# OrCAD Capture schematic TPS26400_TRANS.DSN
size C; title: TPS26400 40-V, 2-A Industrial eFuse With Integrated Reverse; rev: 1.2; note: Datasheet: SLVSDG2G     EVM: SLVUAV3; note: Input Polarity Protection
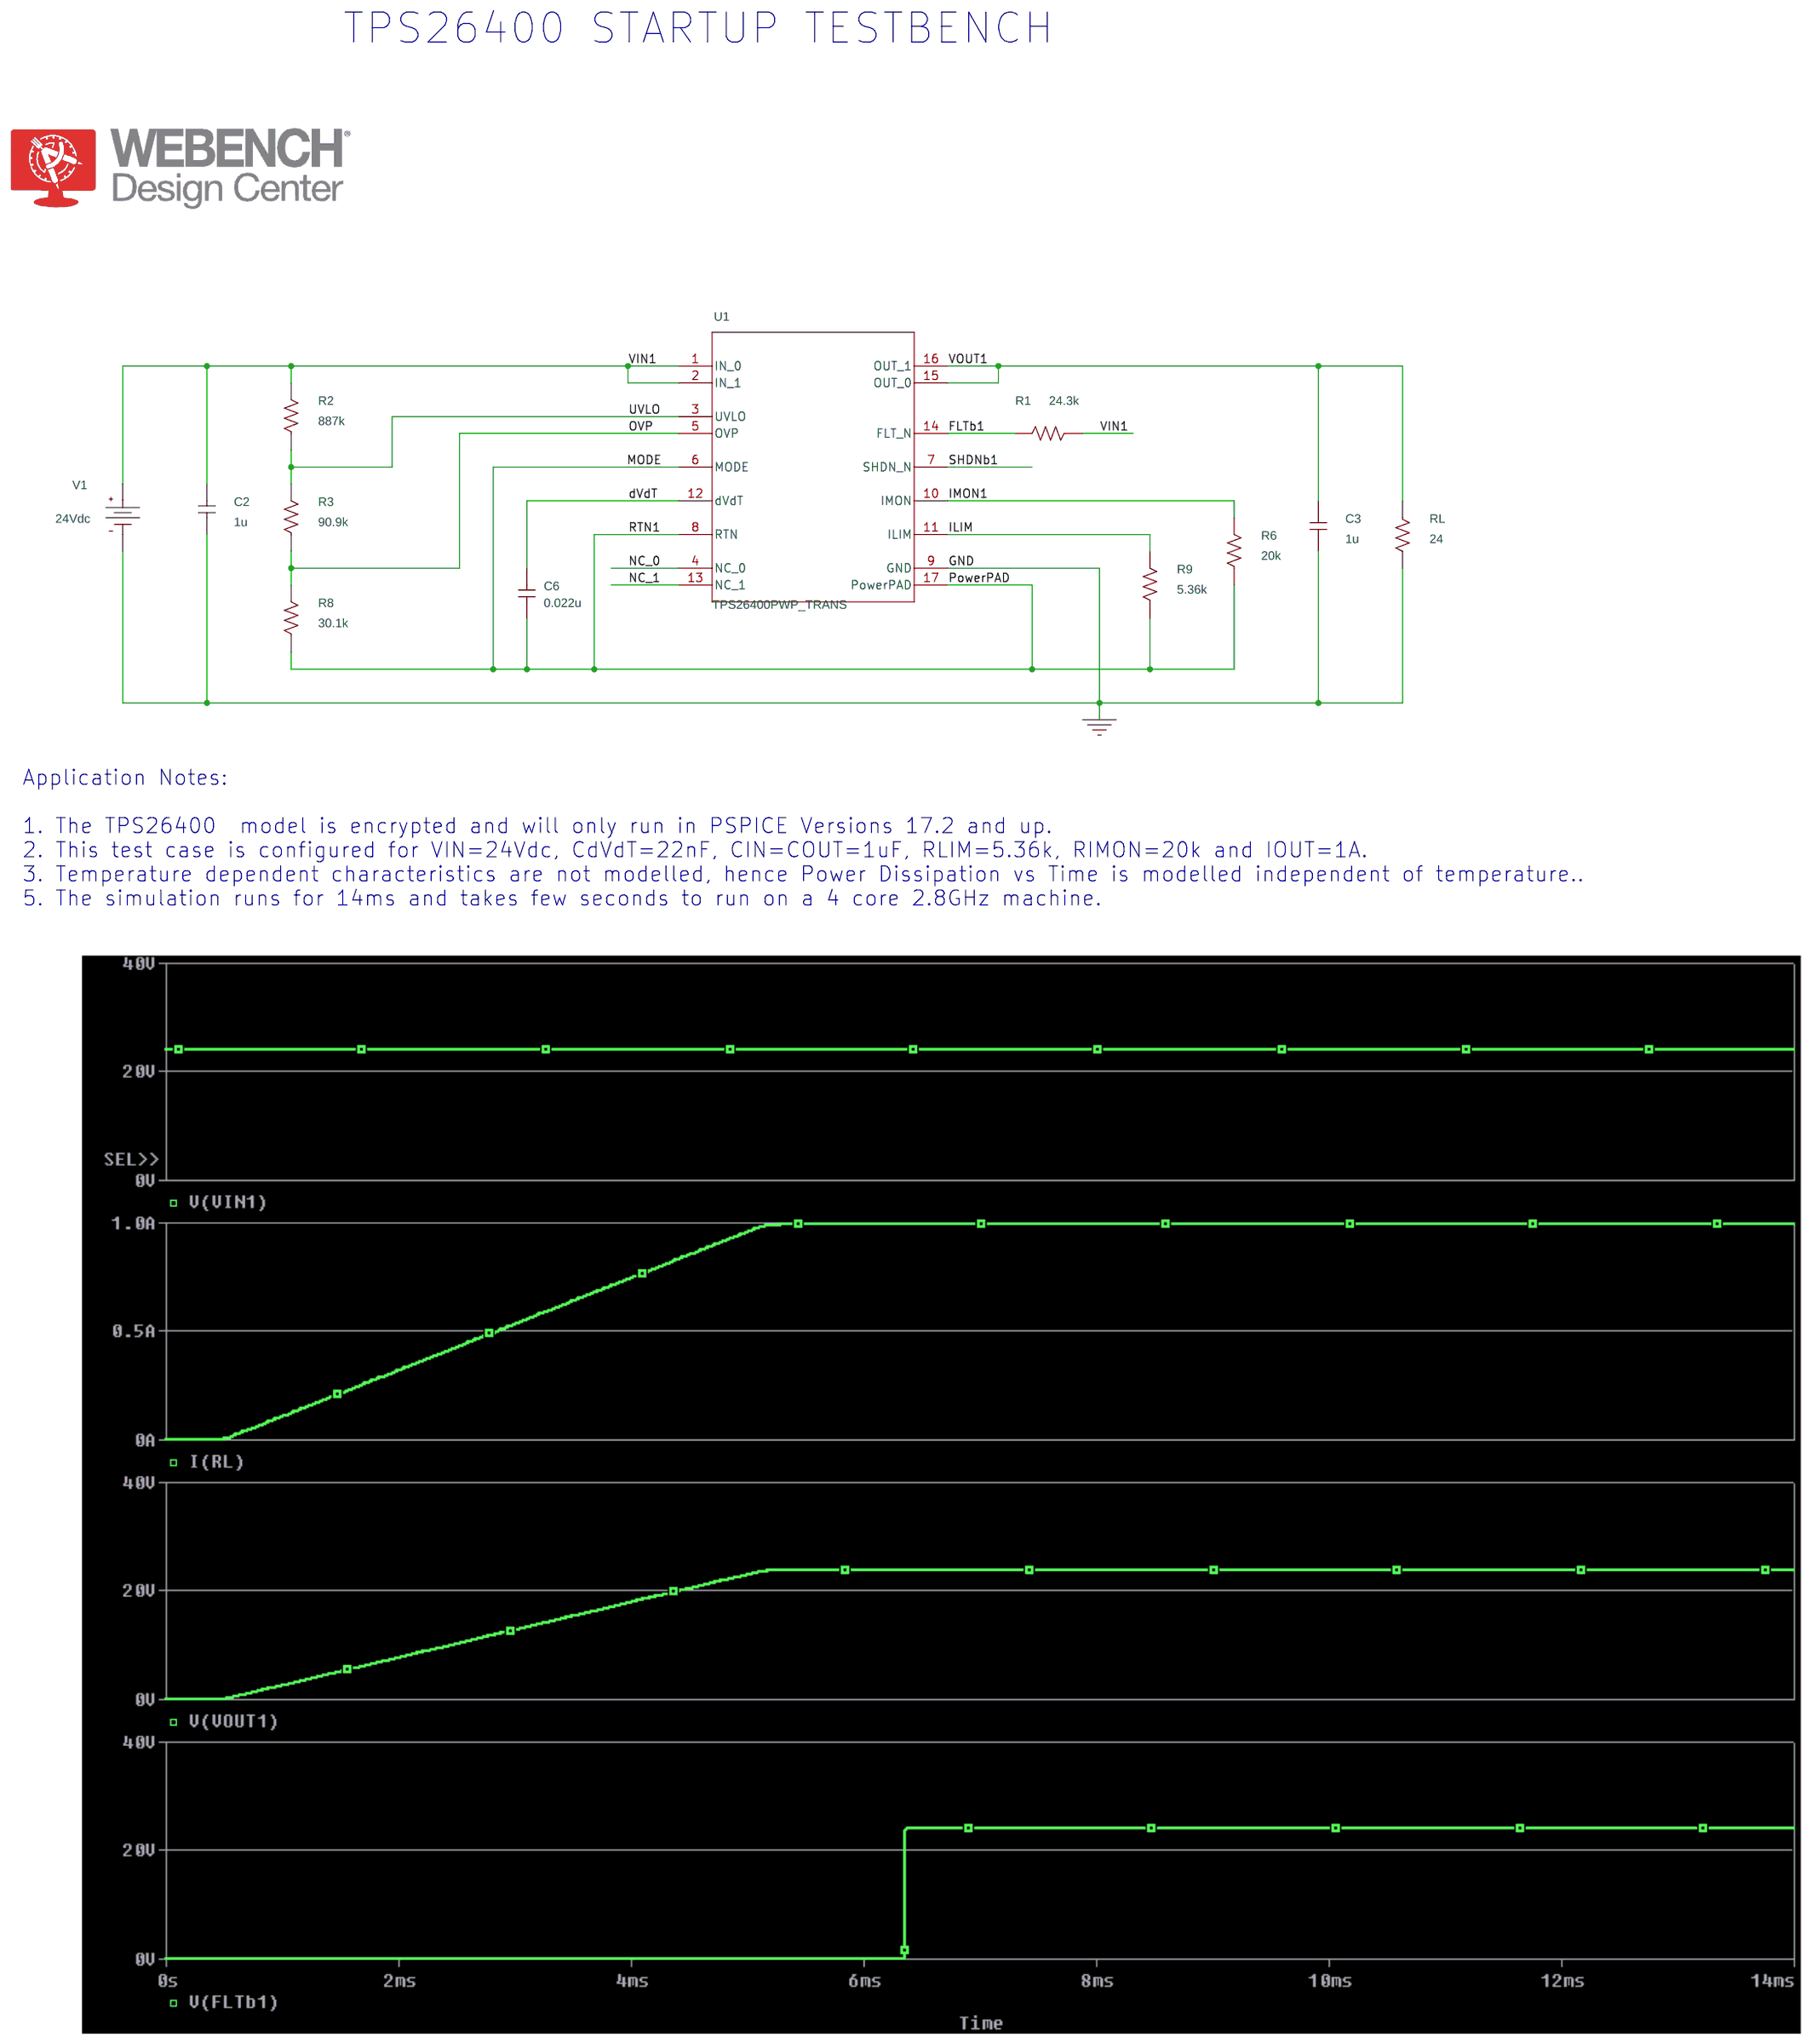
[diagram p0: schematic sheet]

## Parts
C2  1u  [RAD/CK05]
C3  1u  [RAD/CK05]
C6  0.022u  [RAD/CK05]
R1  24.3k  [AX/RC05]
R2  887k  [AX/RC05]
R3  90.9k  [AX/RC05]
R6  20k  [AX/RC05]
R8  30.1k  [AX/RC05]
R9  5.36k  [AX/RC05]
RL  24  [AX/RC05]
U1  TPS26400PWP_TRANS  [PWP0016H-IPC_A]
V1  VDC

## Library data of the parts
C2 C3 C6 = C
R1-R3 R6 R8 R9 RL = R
U1 = TPS26400PWP_TRANS
V1 = VDC: DC: 24Vdc

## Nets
VIN1: C2.1 R1.1 R2.2 U1.1(IN_0) U1.2(IN_1) V1.0(+)
0: C2.2 C3.2 RL.2 U1.9(GND) V1.1(-)
dVdT: C6.1 U1.12(dVdT)
FLTb1: R1.2 U1.14(FLT_N)
ILIM: R9.2 U1.11(ILIM)
IMON1: R6.2 U1.10(IMON)
MODE: C6.2 R6.1 R8.1 R9.1 U1.6(MODE) U1.8(RTN) U1.17(PowerPAD)
NC_0: U1.4(NC_0)
NC_1: U1.13(NC_1)
OVP: R3.1 R8.2 U1.5(OVP)
SHDNb1: U1.7(SHDN_N)
UVLO: R2.1 R3.2 U1.3(UVLO)
VOUT1: C3.1 RL.1 U1.15(OUT_0) U1.16(OUT_1)

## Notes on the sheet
- TPS26400 STARTUP TESTBENCH
- Application Notes:
  1. The TPS26400  model is encrypted and will only run in PSPICE Versions 17.2 and up.
  2. This test case is configured for VIN=24Vdc, CdVdT=22nF, CIN=COUT=1uF, RLIM=5.36k, RIMON=20k and IOUT=1A.
  3. Temperature dependent characteristics are not modelled, hence Power Dissipation vs Time is modelled independent of temperature..
  5. The simulation runs for 14ms and takes few seconds to run on a 4 core 2.8GHz machine.
